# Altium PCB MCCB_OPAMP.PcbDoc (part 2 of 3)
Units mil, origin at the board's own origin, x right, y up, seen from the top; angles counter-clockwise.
Board outline 3937.01 x 3937.01 mil, 2 copper layers (Top Layer, Bottom Layer), stack 62 mil thick; 238 components, 115 nets, 518 pads, 159 vias.
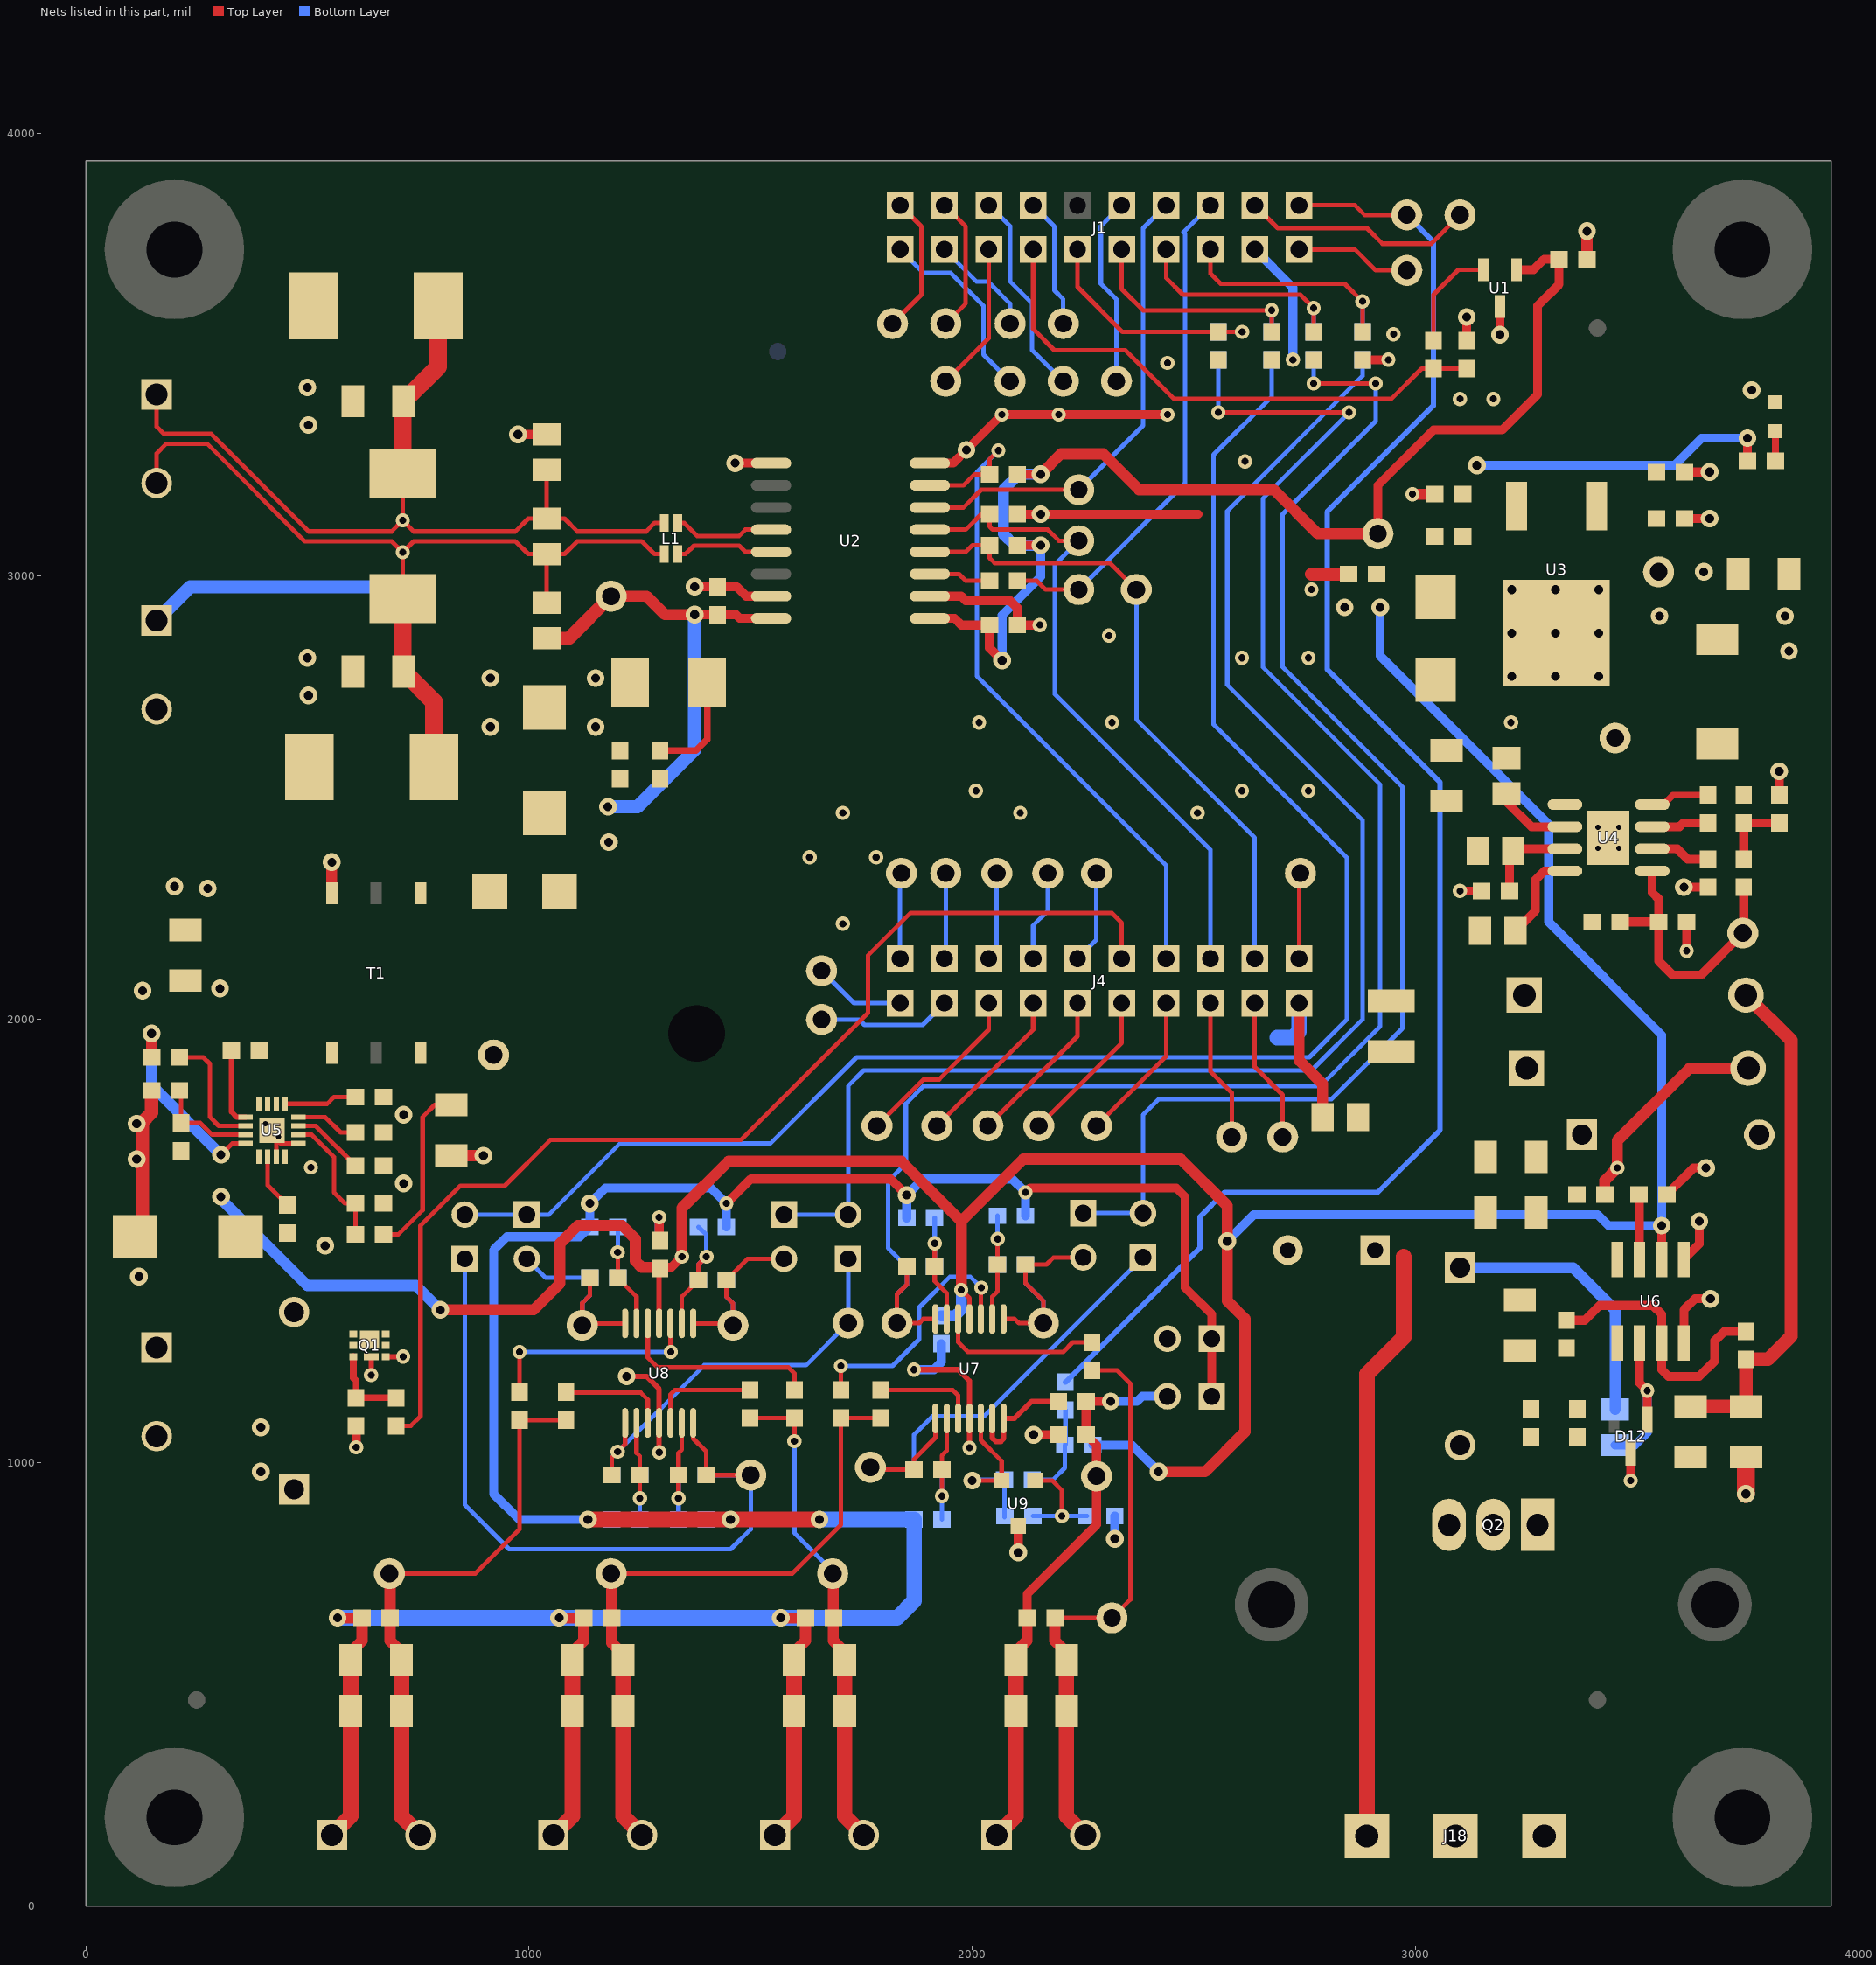
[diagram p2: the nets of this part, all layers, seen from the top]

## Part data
C1 C2 C10 C11 C15 C20 C22 C23 C30 C31 C33 C34 C35 C43: "CAP, CERM, 0.1uF, 25V, +/-5%, X7R, 0603"
C3 C12 C21: "CAP, CERM, 1000pF, 1000V, +/-10%, X7R, 1206"
C4 C7: "CAP, CERM, 1uF, 16V, +/-10%, X7R, 0603"
C5 C8 C29: "CAP, CERM, 0.1uF, 50V, +/-10%, X7R, 0603"
C6: "CAP, TA, 4.7uF, 35V, +/-10%, 1.9 ohm, SMD"
C9: "CAP, CERM, 22uF, 16V, +/-10%, X5R, 1206"
C13 C28: "CAP, TA, 47uF, 35V, +/-10%, 0.3 ohm, SMD"
C14: "CAP, CERM, 1uF, 100V, +/-10%, X7R, 1206"
C16 C25: "CAP, CERM, 0.1uF, 100V, +/-10%, X7R, 0805"
C17 C26 C47 C48 C49 C50: "CAP, CERM, 0.01uF, 25V, +/-5%, C0G/NP0, 0603"
C18: "CAP, CERM, 3300pF, 50V, +/-10%, X7R, 0603"
C19: "CAP, CERM, 1uF, 25V, +/-10%, X5R, 0603"
C24: "CAP, CERM, 22uF, 16V, +/-20%, X5R, 1206"
C27: "CAP, AL, 100uF, 100V, +/-20%, 0.12 ohm, TH"
C32 C36 C37 C38 C39 C40 C41 C42 C44 C45 C46: "CAP, CERM, 100pF, 25V, +/-10%, X7R, 0603"
D1 D3 D5: "Diode, TVS 15V 1500W BIDIR 5% SMC"
D2: "LED SmartLED Green 570NM"
D4: "Diode, Zener, 5.1V, 5W, SMB"
D6: "Diode, Schottky, 20V, 1A, SMA"
D7: "Diode, Zener, 39V, 1W, DO41"
D8: "Diode, Zener, 16V, 1W, DO41"
D9 D11: "Diode, P-N, 1000V, 1A, TH"
D10: library part 1N4007, "Diode, P-N, 1100V, 1A, TH"
D12: "Diode, Switching, 200V, 0.2A, SOT-23"
FB1: library part MMZ1608B102C, "FERRITE CHIP 1000 OHM 300MA 0603"
FID1 FID2 FID3 FID4 FID5 FID6: "Fiducial mark.  There is nothing to buy or mount."
H1 H2 H4 H5: "Machine Screw, Round, #4-40 x 1/4, Nylon, Philips panhead"
H3: library part "MH 3_0.5MM", "Mountin hole, NPTH Drill 3.2mm"
H6 H7 H8 H9: "Standoff, Hex, 0.5\"L #4-40 Nylon"
HS1: library part HEATSINK_513201, "HEATSINK TO-220 W/PINS 1.5\"TALL"
J1 J4: "Header, Male 2x10-pin, 100mil spacing"
J2 J3 J11 J14 J15 J16 J17: "TERMINAL BLOCK 5.08MM VERT 2POS, TH"
J5 J6 J7 J8 J9 J10 J12 J13: "Header, Male 2-pin, 100mil spacing,"
J18: "Terminal Block, 3-pin, 15-A, 5.1mm"
L1: library part IND_ACM2012_SERIES, "Inductor, Common Mode Filter SMD"
L2: library part IND_SRR7032-221M, "Inductor, 220uH .30A SMD"
L3: library part IND_B82422H1332K, "Inductor, Chip, 3.3uH 770MA 1210 10%"
LBL1: library part THT-14-423-10, "Thermal Transfer Printable Labels, 0.650\" W x 0.200\" H - 10,000 per roll"
Logo1: library part TI_Logo, "Texas Instrument Corporate Signature"
Q1: "MOSFET, N-CH, 30V, 22A, SON 2X2 MM"
Q2: "MOSFET, N-CH, 60V, 50A, TO-220AB"
R1 R40 R67 R68 R69 R70 R71: "RES, 100 ohm, 1%, 0.1W, 0603"
R2 R9: "RES, 470 ohm, 1%, 0.125W, 0805"
R3 R39: "RES, 300 ohm, 5%, 0.1W, 0603"
R4 R5 R7: "RES, 10k ohm, 5%, 0.1W, 0603"
R6: "RES, 120 ohm, 5%, 0.125W, 0805"
R8: "RES, 10.0 ohm, 1%, 0.1W, 0603"
R10: "RES, 200 ohm, 1%, 0.1W, 0603"
R11: "RES, 63.4k ohm, 1%, 0.1W, 0603"
R12: "RES, 121k ohm, 0.1%, 0.125W, 0805"
R13 R22: "RES, 10.0k ohm, 1%, 0.1W, 0603"
R14: "RES, 1.00k ohm, 1%, 0.1W, 0603"
R15: "RES, 9.76k ohm, 1%, 0.1W, 0603"
R16: "RES, 53.6k ohm, 0.1%, 0.125W, 0805"
R17 R25: "RES, 100k ohm, 1%, 0.1W, 0603"
R18: "RES, 21.5k ohm, 1%, 0.1W, 0603"
R19 R63: "RES, 30k ohm, 5%, 0.1W, 0603"
R20: "RES, 280k ohm, 1%, 0.1W, 0603"
R21 R23 R29: "RES, 10.0k ohm, 1%, 0.25W, 1206"
R24: "RES, 43.2k ohm, 1%, 0.1W, 0603"
R26 R27 R28 R59: "RES, 68k ohm, 5%, 0.1W, 0603"
R30: "RES, 1.00Meg ohm, 1%, 0.1W, 0603"
R31 R32 R33 R34 R35 R36 R37 R38 R55 R56 R57 R58 R62 R64 R65 R66: "RES, 10k ohm, 0.01%, 0.063W, 0603"
R41 R42: "RES, 1.00k ohm, 1%, 0.25W, 1206"
R43: "RES, 510 ohm, 0.1%, 0.1W, 0603"
R44 R45 R46: "RES, 27k ohm, 5%, 0.1W, 0603"
R47 R48 R49 R50 R51 R52 R53 R54: "RES, 22 ohm, 5%, 0.25W, 1206"
R60: "RES, 47k ohm, 5%, 0.125W, 0805"
R61: "RES, 470 ohm, 5%, 0.1W, 0603"
R72: "RES, 0 ohm, 5%, 0.1W, 0603"
T1: library part "TRNSFMR 760390015", "Transformer 475uH SMD"
TP1 TP2 TP3 TP4 TP5 TP6 TP7 TP8 TP9 TP10 TP11 TP12 TP13 TP14 TP15 TP16 TP17 TP18 TP19 TP20 TP21 TP22 TP23 TP24 TP25 TP26 TP27 TP28 TP29 TP30 TP31 TP32 TP33 TP34 TP35 TP36 TP37 TP38 TP39 TP40 TP41 TP42 TP43 TP44 TP45 TP46 TP47 TP48: "Test Point, O.040 Hole"
U1: "2.7V, 15.6mV/°C, Temperature Sensor, 3-pin SOT-23"
U2: "IC, ISOLATED RS-485 PROFIBUS TRANSCEIVER"
U3: "IC, 300-mA 40-V LOW-DROPOUT REGULATOR WITH 25-uA QUIESCENT CURRENT"
U4: "100V, 600mA Constant On-Time Synchronous Buck Regulator, DDA0008B"
U5: "IC, DC-DC Converter"
U6: "IC, Dual Differential Comparators, 2-36 Vin"
U7 U8: library part LMV324IPW, "LOW-VOLTAGE RAIL-TO-RAIL OUTPUT OPERATIONAL AMPLIFIERS, PW0014A"
U9: "IC, Micropower Shunt Voltage Reference 100 ppm/°C, 45µA-12mA,  Adjustable"
ZZ1: library part AssemblyNoteLabel
ZZ2 ZZ3 ZZ4: library part AssemblyNote

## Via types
v1: diameter 32, hole 16, Top Layer to Bottom Layer, tented both sides, 69 vias
v2: diameter 40, hole 20, Top Layer to Bottom Layer, tented both sides, 68 vias
v3: diameter 40, hole 20, Top Layer to Bottom Layer, 15 vias
v4: diameter 26, hole 12, Top Layer to Bottom Layer, tented both sides, 6 vias
v5: diameter 32, hole 16, Top Layer to Bottom Layer, 1 vias

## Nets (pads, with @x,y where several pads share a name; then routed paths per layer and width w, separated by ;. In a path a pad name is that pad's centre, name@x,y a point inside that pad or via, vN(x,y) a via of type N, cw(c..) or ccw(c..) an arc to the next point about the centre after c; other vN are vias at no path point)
3.3_REF: J1.1 R72.1 TP1.1 | length 3668
  Top Layer w10: J1.1@2737.01,3837.01 2862.99,3837.01 2885,3815 TP1.1@2980,3815
  Bottom Layer w12: R72.1@2210,1181.5 2513,1484.5 2513,1554.64 2568.36,1610 2914,1610 3055,1751 3055,2535 2800,2790 2800,3145 3040,3385 3040,3755 TP1.1@2980,3815
12V: C5.1 C7.1 C9.1 C18.1 D9.2 D11.1 J11.2 L2.2 R15.2 R22.2 TP15.1 U3.1 | length 231.9
  Top Layer w20: R22.2@3566.5,1605 3626.5,1665 v2(3655,1665) ; v1(3611.5,2155) R15.2@3611.5,2220 ; C18.1@3820,2506.5 v2(3820,2560)
  other v2: 395,980 395,1080 3550,2910 3650,3010
16V_C: C29.1 D8.1 D9.1 R21.1 R23.1 R29.1 U6.8
39V: C25.1 C27.1 D7.1 D10.1 J18.1 L3.1 R21.2 R23.2 R60.2 | length 1955.7
  Top Layer w35: J18.1@2890,158 2890,1200 2973,1283 2973,1465
  Bottom Layer w25: D10.1@3100,1440 3354.97,1440 3450,1344.97 R60.2@3450,1120
B: C48.2 J1.10 R68.2 | length 543.9
  Top Layer w10: J1.10@2337.01,3737.01 2337.01,3647.99 2385,3600 v1(2675,3600) C48.2@2675,3551.5
  Bottom Layer w10: R68.2@2675,3551.5 v1(2675,3600)
B_IP: C38.1 J16.2 R35.1 R36.1 R49.2 R53.2 TP47.1 | length 1105.6
  Top Layer w10: R36.1@1498.54,1100.77 R35.1@1598.54,1100.77 v1(1598.54,1048.54)
  Top Layer w25: TP47.1@1685,750 1686.5,748.5 C38.1@1686.5,650 1686.5,598.5 1712.09,572.91 R49.2@1712.09,555
  Top Layer w35: R49.2@1712.09,555 R53.2@1712.09,440 1712.09,202.91 J16.2@1755,160
  Bottom Layer w10: v1(1598.54,1048.54) 1598.54,841.46 1685,755 TP47.1@1685,750
C5V: C10.2 C13.1 C15.1 D6.1 R9.2 R10.2 TP18.1 U2.16 | length 1119.7
  Top Layer w20: v2(1373.5,2913.5) C10.2@1425,2913.5 1466.5,2913.5 1475,2905 U2.16@1545.87,2905
  Top Layer w25: TP18.1@1185,2955 1265,2955 1306.5,2913.5 v2(1373.5,2913.5)
  Top Layer w30: R9.2@1040,2860 1090,2860 TP18.1@1185,2955
  Bottom Layer w30: v2(1178,2480) 1245,2480 1373.5,2608.5 v2(1373.5,2913.5)
  other v2: 1180,2400
EGND: C3.2 C12.1 D1.1 D5.2 J3.2
  other v2: 502.5,2731 500,2816 502.5,3341 500,3426
FSD: J4.9 R39.1 | length 2533.9
  Top Layer w10: R39.1@700,1083.5 733.5,1083.5 755,1105 755,1535 845,1625 945,1625 1048.01,1728.01 1477.57,1728.01 1765,2015.44 1765,2145 1860,2240 2315,2240 2337.01,2217.99 J4.9@2337.01,2137.01
GND: C1.2 C2.1 C4.2 C5.2 C6.2 C7.2 C8.2 C9.2 C11.1 C14.1 C16.1 C19.2 C21.2 C23.1 C24.2 C25.2 C26.2 C27.2 C28.2 C29.2 C30.2 C31.1 C33.2 C35.1 C43.1 C47.1 C48.1 C49.1 C50.1 D2.1 D8.2 D12.3 J1.4 J4.2 J12.2 J18.2 Q1.4 Q1.7 Q2.3 R5.1 R13.1 R14.1 R18.1 R20.1 R24.1 R41.1 R42.1 R62.1 U1.3 U2.2 U2.8 U3.2 U4.1 U4.9 U5.3 U5.4 U5.5 U5.17 U6.4 U6.5 U7.11 U8.11 U9.3 | length 5033
  Top Layer w10: U5.3@429.9,1690.7 U5.17@429.9,1730 ; U5.17@429.9,1735 429.9,1740.5 U5.17@420.1,1750.3 420.1,1739.8 U5.17@429.9,1730 ; U5.5@479.55,1720.65 439.25,1720.65 U5.17@429.9,1730
  Top Layer w12: v1(643.78,1197.79) Q1.7@643.78,1239.41 ; Q1.4@676.32,1239.41 v1(715.98,1239.41) ; v2(1220,1195) 1265,1195 1293.55,1166.45 U8.11@1293.55,1090.06 v1(1293.55,1023.55) ; v1(1868,1210) 1968,1210 1993.54,1184.46 U7.11@1993.54,1100.06 v1(1993.54,1033.55)
  Top Layer w20: v1(610,1035) C33.2@610,1083.5 ; C31.1@1293.54,1503.76 v1(1293.54,1553.54) ; U2.2@1904.13,2955 1975,2955 1985,2945 2085,2945 2101.5,2928.5 C11.1@2101.5,2890 v1(2152,2890) ; U2.8@1904.13,3255 1956.64,3255 v2(1986.64,3285) v1(2066.64,3365) v1(2440,3365) ; R5.1@2101.5,3140 v2(2154,3140) 2509,3140 ; v2(2103.54,797.54) U9.3@2103.54,857.27 ; v2(2138,1063.29) C35.1@2193.5,1063.29 ; C47.1@2880,3488.5 v1(2938.5,3488.5) ; v1(3100,2290) R13.1@3148.5,2290 ; C2.1@3115,3531.5 v2(3115,3585) ; v2(3190,3545) U1.3@3190,3608.66 ; v1(3485,960) D12.3@3485,1022.6 ; U6.4@3605,1270 3605,1345 3630,1370 v2(3665,1370) ; U6.5@3605,1459 3640,1494 v2(3640,1545) ; v2(3605,2298.5) C19.2@3660,2298.5 ; C7.2@3606.5,3130 v3(3663,3130) ; C5.2@3606.5,3235 v3(3663,3235)
  Top Layer w25: C24.2@825,1692.91 v2(897.09,1692.91) ; J4.2@2737.01,2037.01 2737.01,1907.99 2790,1855 C25.2@2790,1780 ; v5@2997.01,3185 C4.2@3043.5,3185 ; C1.2@3386.5,3715 v2(3386.5,3778.5) ; C29.2@3426.5,1605 3426.5,1636.5 v1(3455,1665) 3455,1727 3618,1890 D8.2@3750,1890
  Top Layer w30: C28.2@127.91,1488.09 127.91,1768.91 148.5,1789.5 R18.1@148.5,1840 ; 2765,3005 C8.2@2848.5,3005
  Top Layer w40: v2(3745,930) R42.1@3745,1012.91
  Bottom Layer w20: 1293.54,1503.76 v1(1293.54,1553.54) ; v1(1868,1210) 1913,1210 1930,1227 C43.1@1930,1268.5 ; v2(2321.5,828.5) R62.1@2321.5,880 ; J1.4@2637.01,3737.01 2723,3651.02 v1(2723,3488.5)
  Bottom Layer w35: 2687.39,1959.36 2723.36,1959.36 2737.01,1973.01 J4.2@2737.01,2037.01
  other v1: 508,1666 1708,2216 1633,2366 1783,2366 1708,2466 2108,2466 2508,2466 2008,2516 2608,2516 2758,2516 2015,2670 2315,2670 3215,2670 2608,2816 2758,2816 2308,2866 2765,2970 2615,3259 2195,3365 3100,3400 3175,3400 2440,3481 2950,3546
  other v2: 120,1420 540,1490 717,1630 115,1685 115,1765 717,1785 128,2065 303,2070 3842,2831 3833,2910 3758,3420
  other v3: 3217,2773.89 3315,2773.89 3413,2773.89 3217,2871.89 3315,2871.89 3413,2871.89 3217,2969.89 3315,2969.89 3413,2969.89
  other v4: 435,1735 405,1765 3411.38,2386.38 3458.62,2386.38 3411.38,2433.62 3458.62,2433.62
  other v5: 2993,3185
N: C50.2 J1.12 R70.2 | length 551.1
  Top Layer w10: J1.12@2237.01,3737.01 2237.01,3652.99 2338.5,3551.5 C50.2@2555,3551.5 v1(2608.5,3551.5)
  Bottom Layer w10: R70.2@2555,3551.5 v1(2608.5,3551.5)
N_IP: C39.1 J17.2 R32.1 R50.2 R54.2 TP48.1 | length 1299.8
  Top Layer w10: C39.1@2186.5,650 TP48.1@2315,650 2357,692 2357,1178 2326.5,1208.5 R32.1@2270,1208.5
  Top Layer w25: C39.1@2185.99,650 2185.99,598.5 2211.58,572.91 R50.2@2211.58,555
  Top Layer w35: R50.2@2212.09,562.91 R50.2@2212.09,555 R54.2@2212.09,440 2212.09,202.91 J17.2@2255,160
NetC4_1: C4.1 FB1.1 R3.2 U3.3 | length 687.5
  Top Layer w20: R3.2@3748.5,3260 v3(3748.5,3311.5)
  Bottom Layer w20: v3(3138,3250) 3583.5,3250 3645,3311.5 v3(3748.5,3311.5)
NetC14_2: C14.2 C16.2 L3.2 R12.2 R16.2 U4.2 | length 177.3
  Top Layer w20: C16.2@3205,2513.5 C16.2@3205,2510 3205,2491 3261,2435 U4.2@3336.57,2435
NetC17_1: C17.1 U4.7 | length 130.1
  Top Layer w20: U4.7@3533.43,2435 3595,2435 3603.5,2443.5 C17.1@3660,2443.5
NetC17_2: C17.2 L2.1 R11.1 TP19.1 U4.8 | length 135.5
  Top Layer w15: U4.8@3533.43,2485 3559,2485 3580.5,2506.5 C17.2@3660,2506.5
NetC18_2: C18.2 C20.2 R11.2 | length 162
  Top Layer w20: C20.2@3740,2361.5 R11.2@3740,2443.5 C18.2@3820,2443.5
NetC19_1: C19.1 U4.6 | length 136.3
  Top Layer w20: U4.6@3533.43,2385 3590,2385 3613.5,2361.5 C19.1@3660,2361.5
NetC20_1: C20.1 R14.2 R15.1 TP26.1 U4.5 | length 643
  Top Layer w20: R14.2@3461.5,2220 R15.1@3548.5,2220 ; U4.5@3533.43,2335 3533.43,2286.57 3548.5,2271.5 R15.1@3548.5,2220 ; C20.1@3740,2298.5 3740,2197 TP26.1@3738,2195 3643,2100 3580,2100 3548.5,2131.5 R15.1@3548.5,2220
NetC22_1: C22.1 T1.1 U5.10 U5.11 U5.12
NetC22_2: C22.2 U5.13 | length 175.3
  Top Layer w12: C22.2@328.5,1930 328.5,1791.5 340.05,1779.95 U5.13@360.55,1779.95
NetC23_2: C23.2 U5.9 | length 165.2
  Top Layer w10: U5.9@449.6,1809.7 544.7,1809.7 560,1825 C23.2@608.5,1825
NetC24_1: C24.1 R25.1 T1.3 TP29.1 | length 397.5
  Top Layer w10: R25.1@671.5,1515 705,1515 760,1570 760,1780 787.09,1807.09 C24.1@825,1807.09
NetC26_1: C26.1 U5.7 | length 166.3
  Top Layer w10: U5.7@479.55,1760.05 518.45,1760.05 C26.1@608.5,1670
NetC32_1: C32.1 R57.2 R59.1 U8.2 | length 308.3
  Top Layer w10: U8.2@1344.73,1314.47 1344.73,1374.95 C32.1@1382.05,1412.27 1382.05,1447.05 v1(1400,1465)
  Bottom Layer w10: R59.1@1382.05,1412.27 1382.05,1447.05 v1(1400,1465) 1400,1514.31 R57.2@1382.05,1532.27
NetC32_2: C32.2 J9.2 R59.2 TP41.1 U8.1 | length 451.9
  Top Layer w10: U8.1@1370.32,1314.47 TP41.1@1455.53,1314.47 ; TP41.1@1460,1310 1460,1360 1445.04,1374.96 C32.2@1445.04,1412.27 1492.77,1460 J9.2@1575,1460
  Bottom Layer w10: R59.2@1445.04,1412.27 1445.04,1374.96 1460,1360 TP41.1@1460,1310
NetC33_1: C33.1 Q1.3 R39.2 | length 175.5
  Top Layer w15: Q1.3@603.68,1239.41 603.68,1191.32 610,1185 C33.1@610,1146.5 ; C33.1@620,1146.5 R39.2@700,1146.5
NetC34_1: C34.1 R29.2 R30.2 R43.1 U6.1
NetC34_2: C34.2 Q2.1 R43.2
NetC40_1: C40.1 R26.1 R55.2 U7.2 | length 295.6
  Top Layer w10: U7.2@2044.72,1324.47 2044.72,1374.72 2057.05,1387.05 R26.1@2057.05,1447.27 v1(2057.05,1505)
  Bottom Layer w10: C40.1@2057.05,1447.27 v1(2057.05,1505) R55.2@2057.05,1557.27
NetC40_2: C40.2 J5.2 R26.2 TP39.1 U7.1 | length 527.8
  Top Layer w10: U7.1@2070.32,1324.47 2095.53,1324.47 2105,1315 TP39.1@2160,1315 2160,1365 2120.04,1404.96 R26.2@2120.04,1447.27 2167.27,1447.27 2183.29,1463.29 J5.2@2250,1463.29
  Bottom Layer w10: C40.2@2120.04,1447.27 2120.04,1404.96 2160,1365 TP39.1@2160,1315
NetC41_1: C41.1 R27.1 R56.2 U7.6 | length 291.8
  Top Layer w10: v1(1915,1495) R27.1@1915.04,1442.27 1915.04,1409.96 1942.36,1382.64 U7.6@1942.36,1324.47
  Bottom Layer w10: v1(1915,1495) v1(1915,1495) C41.1@1915.04,1442.27 ; v1(1915,1495) R56.2@1915.04,1552.27
NetC41_2: C41.2 R27.2 R70.1 TP38.1 U7.7 | length 3896.7
  Top Layer w10: R27.2@1852.05,1442.27 1852.05,1402.05 1830,1380 TP38.1@1830,1315 1880,1315 1889.47,1324.47 U7.7@1916.77,1324.47 ; v1(2555,3370) v1(2850,3370)
  Bottom Layer w10: TP38.1@1830,1315 1830,1380 1852.05,1402.05 C41.2@1852.05,1442.27 1810,1484.31 1810,1635 1850,1675 1850,1810 1890,1850 2785,1850 2920,1985 2920,2530 2655,2795 2655,3175 v1(2850,3370) ; v1(2555,3370) R70.1@2555,3488.5
NetC42_1: C42.1 R28.1 R58.2 U8.6 | length 293
  Top Layer w10: v1(1200.04,1474.96) R28.1@1200.04,1417.27 1242.37,1374.94 U8.6@1242.37,1314.47
  Bottom Layer w10: C42.1@1200.04,1417.27 v1(1200.04,1474.96) R58.2@1200.04,1532.27
NetC42_2: C42.2 J8.2 R28.2 TP40.1 U8.7 | length 487
  Top Layer w10: R28.2@1137.05,1417.27 1137.05,1377.05 1120,1360 TP40.1@1120,1310 1124.47,1314.47 U8.7@1216.78,1314.47
  Bottom Layer w10: J8.2@995,1460 1037.73,1417.27 C42.2@1137.05,1417.27 1137.05,1377.05 1120,1360 TP40.1@1120,1310
NetC44_1: C44.1 R44.1 R65.2 U7.9 | length 292.3
  Top Layer w10: v1(1931.5,925) R44.1@1931.5,985 1931.5,1016.5 1942.36,1027.36 U7.9@1942.36,1100.06
  Bottom Layer w10: R65.2@1931.5,872.27 v1(1931.5,925) 1931.5,935 C44.1@1931.5,985
NetC44_2: C44.2 J6.1 R44.2 TP42.1 U7.8 | length 1096.8
  Top Layer w10: TP42.1@1770,990 1775,985 R44.2@1868.5,985 1868.5,1008.5 1916.77,1056.77 U7.8@1916.77,1100.06
  Bottom Layer w10: TP42.1@1770,990 1775,985 C44.2@1868.5,985 1868.5,1063.5 1910,1105 2026.71,1105 J6.1@2385,1463.29
NetC45_1: C45.1 R46.1 R66.2 U8.9 | length 273.2
  Top Layer w10: U8.9@1242.37,1090.06 1242.37,1022.63 1250.04,1014.96 R46.1@1250.04,972.27 v1(1250.04,920)
  Bottom Layer w10: R66.2@1250.04,872.27 v1(1250.04,920) C45.1@1250.04,972.27
NetC45_2: C45.2 J10.1 R46.2 TP37.1 U8.8 | length 973.3
  Top Layer w10: R46.2@1187.05,972.27 1187.05,1012.05 v1(1200,1025) 1216.78,1041.78 U8.8@1216.78,1090.06
  Bottom Layer w10: C45.2@1187.05,972.27 1187.05,1012.05 v1(1200,1025) 1395,1220 1625,1220 TP37.1@1720,1315 J10.1@1720,1460
NetC46_1: C46.1 R45.1 R64.2 U8.13 | length 273.2
  Top Layer w10: v1(1337.05,920) R45.1@1337.05,972.27 1337.05,1022.05 1344.73,1029.73 U8.13@1344.73,1090.06
  Bottom Layer w10: R64.2@1337.05,872.27 v1(1337.05,920) C46.1@1337.05,972.27
NetC46_2: C46.2 J7.1 R45.2 TP43.1 U8.14 | length 1712.3
  Top Layer w10: U8.14@1370.32,1090.06 1370.32,1054.68 1400.04,1024.96 R45.2@1400.04,972.27 TP43.1@1500,972.27
  Bottom Layer w10: J7.1@855,1460 855,905 955,805 1455,805 1500,850 TP43.1@1500,972.27 C46.2@1400.04,972.27
NetD2_2: D2.2 R3.1 | length 68.1
  Top Layer w15: D2.2@3810,3327.52 3811.5,3326.02 R3.1@3811.5,3260
NetD4_1: D4.1 R10.1 | length 245.6
  Top Layer w15: R10.1@1295,2606.5 1376.5,2606.5 1402,2632 D4.1@1402,2760
NetD6_2: D6.2 T1.4
NetD7_2: D7.2 R31.2 R41.2 R42.2 | length 1166.7
  Top Layer w30: R41.2@3620,1127.09 R42.2@3745,1127.09 R31.2@3745,1233.5 3795,1233.5 3847.01,1285.51 3847.01,1952.99 D7.2@3745,2055
NetD10_2: D10.2 J18.3 Q2.2
NetD11_2: D11.2 J11.1 Q1.1 Q1.2 Q1.5 Q1.6 Q1.8
NetD12_1: D12.1 R60.1 U6.2 | length 358.8
  Top Layer w20: U6.2@3505,1270 3505,1180 v1(3522.4,1162.6) D12.1@3522.4,1097.4
  Bottom Layer w20: R60.1@3450,1040 3495,1040 3522.4,1067.4 v1(3522.4,1162.6)
NetJ1_2: J1.2 TP3.1 | length 262.5
  Top Layer w10: J1.2@2737.01,3737.01 2862.99,3737.01 2910,3690 TP3.1@2980,3690
NetJ1_3: J1.3 TP2.1 | length 526
  Top Layer w10: J1.3@2637.01,3837.01 2689.02,3785 2890,3785 2925,3750 3035,3750 TP2.1@3100,3815
NetJ1_9: J1.9 TP11.1 | length 431
  Bottom Layer w10: TP11.1@2325,3440 2325,3625 2290,3660 2290,3790 J1.9@2337.01,3837.01
NetJ1_13: J1.13 TP7.1 | length 295.2
  Bottom Layer w10: J1.13@2137.01,3837.01 2185,3789.02 2185,3645 2205,3625 TP7.1@2205,3570
NetJ1_15: J1.15 TP10.1 | length 467.2
  Bottom Layer w10: J1.15@2037.01,3837.01 2037.99,3837.01 2085,3790 2085,3665 2135,3615 2135,3510 TP10.1@2205,3440
NetJ1_16: J1.16 TP8.1 | length 337.2
  Top Layer w10: TP8.1@1940,3440 2037,3537 J1.16@2037.01,3737.01
NetJ1_17: J1.17 TP5.1 | length 305.5
  Top Layer w10: J1.17@1937.01,3837.01 1985,3789.02 1985,3615 TP5.1@1940,3570
NetJ1_18: J1.18 TP6.1 | length 243.5
  Bottom Layer w10: J1.18@1937.01,3737.01 2009.02,3665 2035,3665 2085,3615 TP6.1@2085,3570
NetJ1_19: J1.19 TP4.1 | length 313.8
  Top Layer w10: TP4.1@1820,3570 1885,3635 1885,3789.02 J1.19@1837.01,3837.01
NetJ1_20: J1.20 TP9.1 | length 435.5
  Bottom Layer w10: J1.20@1837.01,3737.01 1890,3684.02 1950.98,3684.02 2025,3610 2025,3500 TP9.1@2085,3440
NetJ4_1: J4.1 TP25.1 | length 190
  Top Layer w10: J4.1@2737.01,2137.01 TP25.1@2737.01,2327.01
NetJ4_4: J4.4 TP36.1 | length 328.1
  Top Layer w10: J4.4@2637.01,2037.01 2637.01,1892.99 2700,1830 TP36.1@2700,1735
NetJ4_6: J4.6 TP35.1 | length 321.9
  Top Layer w10: J4.6@2537.01,2037.01 2537.01,1882.99 2585,1835 TP35.1@2585,1735
NetJ4_8: J4.8 TP34.1 | length 342
  Top Layer w10: TP34.1@2280,1760 2437.01,1917.01 J4.8@2437.01,2037.01
NetJ4_10: J4.10 TP33.1 | length 354.5
  Top Layer w10: TP33.1@2150,1760 2337.01,1947.01 J4.10@2337.01,2037.01
NetJ4_11: J4.11 TP24.1 | length 210.8
  Bottom Layer w10: J4.11@2237.01,2137.01 2280,2180 TP24.1@2280,2330
NetJ4_12: J4.12 TP32.1 | length 360.7
  Top Layer w10: TP32.1@2035,1760 2237.01,1962.01 J4.12@2237.01,2037.01
NetJ4_13: J4.13 TP23.1 | length 206.7
  Bottom Layer w10: J4.13@2137.01,2137.01 2137.01,2212.01 2170,2245 TP23.1@2170,2330
NetJ4_14: J4.14 TP31.1 | length 366.9
  Top Layer w10: TP31.1@1920,1760 2137.01,1977.01 J4.14@2137.01,2037.01
NetJ4_15: J4.15 TP22.1 | length 200.4
  Bottom Layer w10: J4.15@2037.01,2137.01 2055,2155 TP22.1@2055,2330
NetJ4_16: J4.16 TP30.1 | length 401.9
  Top Layer w10: TP30.1@1785,1760 1890,1865 1925,1865 2037.01,1977.01 J4.16@2037.01,2037.01
NetJ4_17: J4.17 TP21.1 | length 190
  Bottom Layer w10: J4.17@1940,2140 TP21.1@1940,2330
NetJ4_18: J4.18 TP28.1 | length 302.3
  Bottom Layer w10: TP28.1@1660,2000 1745,2000 1757,1988 1888,1988 J4.18@1937.01,2037.01
NetJ4_19: J4.19 TP20.1 | length 194.2
  Bottom Layer w10: J4.19@1837.01,2137.01 1837.01,2327.01 TP20.1@1840,2330
NetJ4_20: J4.20 TP27.1 | length 207.2
  Bottom Layer w10: TP27.1@1660,2110 1732.99,2037.01 J4.20@1837.01,2037.01
NetJ5_1: J5.1 J6.2 R69.1 | length 2869.8
  Top Layer w10: v1(2770,3435) v1(2910,3435)
  Bottom Layer w10: J5.1@2250,1563.29 J6.2@2385,1563.29 2385,1785 2420,1820 2810,1820 2970,1980 2970,2525 2700,2795 2700,3140 2910,3350 v1(2910,3435) ; v1(2770,3435) R69.1@2770,3488.5
NetJ7_2: J7.2 J8.1 R68.1 | length 3839.7
  Bottom Layer w10: J7.2@855,1560 1045,1560 1205,1720 1544,1720 1739,1915 2760,1915 2845,2000 2845,2365 2544,2666 2544,3274 2675,3405 R68.1@2675,3488.5
NetJ9_1: J9.1 J10.2 R67.1 | length 3398.3
  Bottom Layer w10: J9.1@1575,1560 J10.2@1720,1560 1720,1850 1755,1885 2765,1885 2880,2000 2880,2450 2575,2755 2575,3147 2880,3452 R67.1@2880,3488.5
NetL1_1: L1.1 U2.13 | length 224.5
  Top Layer w10: L1.1@1335,3050 1353,3050 1372,3069 1474,3069 1488,3055 U2.13@1545.87,3055
NetL1_2: L1.2 U2.12 | length 228.7
  Top Layer w10: L1.2@1335,3120 1350,3120 1379,3091 1474,3091 1488,3105 U2.12@1545.87,3105
NetR1_1: R1.1 U1.2 | length 239.4
  Top Layer w10: R1.1@3040,3531.5 3040,3635 3096.34,3691.34 U1.2@3152.6,3691.34
NetR8_2: R8.2 U2.3 | length 140.6
  Top Layer w10: U2.3@1904.13,3005 1970,3005 1985,2990 R8.2@2038.5,2990
NetR12_1: R12.1 R13.2 U4.3 | length 217.1
  Top Layer w20: R13.2@3211.5,2290 3211.5,2380 R12.1@3220,2380 3225,2385 U4.3@3336.57,2385
NetR16_1: R16.1 U4.4 | length 208.5
  Top Layer w20: R16.1@3225,2200 3270,2245 3270,2315 3290,2335 U4.4@3336.57,2335
NetR17_1: R17.1 U5.14 | length 283.5
  Top Layer w10: R17.1@211.5,1915 265,1915 280,1900 280,1780 299.95,1760.05 U5.14@360.55,1760.05
NetR18_2: R18.2 R19.1 U5.15 | length 226.4
  Top Layer w10: R18.2@215,1836.5 R19.1@215,1766.5 258.5,1766.5 284.65,1740.35 U5.15@360.55,1740.35
NetR20_2: R20.2 U5.8 | length 143.3
  Top Layer w10: U5.8@479.55,1779.75 540.25,1779.75 575,1745 R20.2@608.5,1745
NetR22_1: R22.1 U6.7 | length 146.6
  Top Layer w20: R22.1@3503.5,1605 3505,1603.5 U6.7@3505,1459
NetR24_2: R24.2 R25.2 U5.6 | length 310.2
  Top Layer w10: U5.6@479.55,1740.35 509.65,1740.35 560,1690 560,1610 585,1585 R24.2@608.5,1585 R25.2@608.5,1515
NetR30_1: R30.1 R31.1 U6.3 | length 626.8
  Top Layer w20: R30.1@3340,1321.5 3381.5,1321.5 3415,1355 3535,1355 3555,1335 U6.3@3555,1270 3555,1210 3570,1195 3640,1195 3675,1230 3675,1275 3696.5,1296.5 R31.1@3745,1296.5
NetR32_2: R32.2 U7.5 | length 372.5
  Top Layer w10: U7.5@1967.95,1324.47 1967.95,1272.05 1990,1250 2205,1250 2226.5,1271.5 R32.2@2270,1271.5
NetR33_2: R33.2 U7.3 | length 578.6
  Top Layer w10: R33.2@1703.54,1163.76 v1(1703.54,1218.54) ; U7.3@2019.13,1324.47 v1@2019.13,1395.87
  Bottom Layer w10: v1(1703.54,1218.54) 1820,1218.54 1880,1278.54 1880,1350.46 1949.54,1420 1995,1420 v1(2020,1395)
NetR34_2: R34.2 U7.10 | length 231.2
  Top Layer w10: R34.2@1793.54,1163.76 1956.24,1163.76 1967.95,1152.05 U7.10@1967.95,1100.06
NetR35_2: R35.2 U8.5 | length 460.4
  Top Layer w10: U8.5@1267.96,1314.47 1267.96,1237.04 1290,1215 1585,1215 1598.54,1201.46 R35.2@1598.54,1163.76
NetR36_2: R36.2 U8.12 | length 247.5
  Top Layer w10: U8.12@1319.14,1090.06 1319.14,1154.14 1328.76,1163.76 R36.2@1498.54,1163.76
NetR37_2: R37.2 U8.3 | length 496.3
  Top Layer w10: R37.2@978.54,1158.76 v1(978.54,1250) ; v1@1319.14,1250.86 U8.3@1319.14,1314.47
  Bottom Layer w10: v1(978.54,1250) v1(1320,1250)
NetR38_2: R38.2 U8.10 | length 243.3
  Top Layer w10: R38.2@1083.54,1158.76 1251.24,1158.76 1267.96,1142.04 U8.10@1267.96,1090.06
NetR40_1: R40.1 U7.13 U7.14 | length 260.2
  Top Layer w12: U7.13@2044.72,1100.06 2044.72,1056.28 2053,1048 2064,1048 2070.32,1054.32 U7.14@2070.32,1100.06 2095.06,1100.06 2133.29,1138.29 R40.1@2193.5,1138.29
NetR61_1: R61.1 R63.2 U7.12 U9.2 | length 384.3
  Top Layer w10: v2(1999.77,959.77) U9.2@2066.04,959.77 2066.04,1003.96 2019.13,1050.87 U7.12@2019.13,1100.06
  Bottom Layer w10: v2(1999.77,959.77) 2002.27,962.27 R61.1@2072.05,962.27 R63.2@2072.05,877.27
NetR61_2: R61.2 R71.2 R72.2 | length 215
  Bottom Layer w10: R61.2@2135.04,962.27 2182.27,962.27 2208.5,988.5 R71.2@2208.5,1040 2210,1041.5 R72.2@2210,1118.5
NetR62_2: R62.2 R63.1 U9.1 | length 250
  Top Layer w10: U9.1@2141.04,959.77 2180.23,959.77 2202,938 v1(2202,880)
  Bottom Layer w10: R63.1@2136.5,880 v1(2202,880) R62.2@2258.5,880
PGND: C10.1 C13.2 C15.2 C21.1 D4.2 J3.1 R2.1 T1.6 U2.9 U2.15 | length 1018.8
  Top Layer w20: v2(975,3320) R2.1@1040,3320 ; v2(1373.5,2976.5) C10.1@1425,2976.5 1468.5,2976.5 1490,2955 U2.15@1545.87,2955 ; v2(1465,3255) U2.9@1545.87,3255
  Top Layer w25: T1.6@555,2284.84 v2(555,2355)
  Bottom Layer w30: J3.1@160,2900 236,2976 750,2976
  other v2: 275,2295.5 200,2300 913,2660 1150,2660 913,2770 1150,2770
R: C47.2 J1.6 R67.2 | length 560.1
  Top Layer w10: J1.6@2537.01,3737.01 2537.01,3682.99 2560,3660 2840,3660 v1(2880,3620) C47.2@2880,3551.5
  Bottom Layer w10: R67.2@2880,3551.5 v1(2880,3620)
R_IP: C36.1 J14.2 R37.1 R38.1 R47.2 R51.2 TP45.1 | length 1301.7
  Top Layer w10: TP45.1@686.5,748.5 687.99,750 878.54,750 978.54,850 R37.1@978.54,1095.77 R38.1@1083.54,1095.77
  Top Layer w25: TP45.1@686.5,748.5 C36.1@686.5,650 686.5,598.5 712.09,572.91 R47.2@712.09,555
  Top Layer w35: R47.2@712.09,555 R51.2@712.09,440 712.09,202.91 J14.2@755,160
RS485_CHIP_EN: J4.7 R4.1 U2.7 | length 1550
  Top Layer w10: U2.7@1904.13,3205 1980,3205 2005,3230 R4.1@2038.5,3230 2038.5,3263.5 v1(2058.5,3283.5)
  Bottom Layer w10: v1(2058.5,3283.5) 2010,3235 2010,2775 2437.01,2347.99 J4.7@2437.01,2137.01
RS485_ISO_A: C3.1 D1.2 D3.1 J2.1 L1.3 R2.2 R6.1 | length 1995.4
  Top Layer w10: J2.1@160,3410 160,3337.58 176.58,3321 282.95,3321 ; 282.82,3321.12 282.95,3321 ; D3.1@715,3230.49 v1(715,3126) ; R2.2@1040,3240 R6.1@1040,3130 ; L1.3@1305,3120 1283,3120 1264,3101 1109,3101 1080,3130 R6.1@1040,3130 ; 282.95,3321 502.95,3101 690,3101 v1(715,3126) ; v1(715,3126) 740,3101 969,3101 998,3130 R6.1@1040,3130
  Top Layer w40: D3.1@715,3230.49 715,3392.91 C3.1@717.09,3395 795.15,3473.06 D1.2@795.15,3610
RS485_ISO_B: C12.2 D3.2 D5.1 J2.2 L1.4 R6.2 R9.1 | length 1992.3
  Top Layer w10: J2.2@160,3210 160,3277.26 181.74,3299 273.83,3299 493.83,3079 500.89,3079 690,3079 v1(715,3054) ; D3.2@715,2949.51 v1(715,3054) ; R9.1@1040,2940 R6.2@1040,3050 ; L1.4@1305,3050 1283,3050 1254,3079 1109,3079 1080,3050 R6.2@1040,3050 ; v1(715,3054) 740,3079 969,3079 998,3050 R6.2@1040,3050
  Top Layer w40: D3.2@715,2949.51 715,2787.09 C12.2@717.09,2785 785.49,2716.59 D5.1@785.49,2570
RS485_RX_EN: J4.3 R7.1 TP17.1 U2.4 | length 1473.8
  Top Layer w10: U2.4@1904.13,3055 1985,3055 2000,3070 R7.1@2038.5,3070 2038.5,3041.5 2050,3030 2310,3030 TP17.1@2370,2970
  Bottom Layer w10: TP17.1@2370,2970 2370,2677.01 2637.01,2410 J4.3@2637.01,2137.01
RS485_TX_EN: J4.5 R5.2 TP14.1 U2.5 | length 1483.8
  Top Layer w10: U2.5@1904.13,3105 1985,3105 R5.2@2020,3140 ; R5.2@2038.5,3140 2038.5,3112.2 2045.7,3105 2170,3105 2195,3080 TP14.1@2240,3080
  Bottom Layer w10: TP14.1@2240,3080 2186,3026 2186,2734 2537.01,2382.99 J4.5@2537.01,2137.01
TEMP: C2.2 J1.14 R1.2 | length 1250.8
  Top Layer w10: J1.14@2137.01,3737.01 2137.01,3557.99 2185,3510 2345,3510 2455,3400 2945,3400 3013.5,3468.5 R1.2@3040,3468.5 C2.2@3115,3468.5
UC3.3V: C1.1 C6.1 C8.1 C11.2 C28.1 C30.1 C31.2 C43.2 FB1.2 R4.2 R7.2 R17.2 R19.2 R71.1 TP13.1 U1.1 U2.1 U5.1 U5.2 U5.16 U6.6 U7.4 U8.4 | length 10377.3
  Top Layer w10: v2(305,1695) 330.65,1720.65 U5.16@360.55,1720.65 ; U5.2@410.2,1690.7 410.2,1626.3 C30.1@455,1581.5 ; v1(1975,1390) 1993.54,1371.46 U7.4@1993.54,1324.47
  Top Layer w12: U8.4@1293.55,1314.47 C31.2@1293.55,1440.77
  Top Layer w20: C31.2@1293.54,1440.77 1320.77,1440.77 v1(1345,1465) ; U2.1@1904.13,2905 1960,2905 1975,2890 C11.2@2038.5,2890 2038.5,2838.5 v2(2067.01,2810) ; R7.2@2101.5,3070 v2(2154,3070) ; R4.2@2101.5,3230 v2(2154,3230) ; TP13.1@2915,3096 2915,3205 3040,3330 3195,3330 3275,3410 3275,3610 3323.5,3658.5 C1.1@3323.5,3715 3289.45,3715 3265.79,3691.34 U1.1@3227.4,3691.34 ; U6.6@3555,1459 v2(3555,1535)
  Top Layer w25: R17.2@148.5,1915 v2(148.5,1968.5) ; v2(800,1345) 1010,1345 1070,1405 1070,1495 1110,1535 1210,1535 1240,1505 1240,1455 1254.23,1440.77 C31.2@1293.55,1440.77 ; v1(1345,1465) 1345,1575 1450,1680 1840,1680 1975,1545 ; v1(1975,1390) 1975,1545 ; v2(2154,3230) 2200,3276 2295,3276 2376,3195 2680,3195 2779,3096 TP13.1@2915,3096 ; v2(2420,980) 2525,980 2615,1070 2615,1325 2575,1365 v2(2575,1500) 2575,1580 2470,1685 2115,1685 1975,1545
  Bottom Layer w20: v2(2067.01,2810) 2067.01,2912.01 2154,2999 v2(2154,3070) ; R71.1@2271.5,1040 2360,1040 v2(2420,980) ; v2(2575,1500) 2635,1560 3410,1560 3435,1535 v2(3555,1535) 3555,1965 3300,2220 3300,2440 2920,2820 v3(2920,2930)
  Bottom Layer w25: v2(148.5,1968.5) 148.5,1851.5 v2(305,1695) ; v2@305,1595 500,1400 745,1400 v2(800,1345) ; C43.2@1930,1331.5 1961.5,1331.5 1975,1345 v1(1975,1390) ; v2(2154,3070) 2095,3070 2070,3095 2070,3195 2105,3230 v2(2154,3230)
  other v2: 305,1600
  other v3: 2840,2930
UCA1RXD: J1.5 R8.1 TP16.1 | length 1140
  Top Layer w10: R8.1@2101.5,2990 2145,2990 2165,2970 TP16.1@2240,2970
  Bottom Layer w10: TP16.1@2240,2970 2480.01,3210.01 2480.01,3772.39 2476.2,3776.2 J1.5@2537.01,3837.01
UCA1TXD: J1.7 TP12.1 U2.6 | length 1076
  Top Layer w10: U2.6@1904.13,3155 1980,3155 2020,3195 TP12.1@2240,3195
  Bottom Layer w10: TP12.1@2240,3195 2385,3340 2385,3785 J1.7@2437.01,3837.01
VCC/2: C35.2 C39.2 J13.2 J17.1 R40.2 R50.1 R54.1 TP44.1 | length 1269.6
  Top Layer w20: C39.2@2123.5,650 2123.5,703.5 2280,860 TP44.1@2280,970 2280,1039.79 C35.2@2256.5,1063.29 R40.2@2256.5,1138.29 v2(2312,1138.29)
  Top Layer w25: R50.1@2097.41,555 2097.41,572.91 2123,598.5 C39.2@2123,650
  Top Layer w35: J17.1@2055,160 2097.91,202.91 R54.1@2097.91,440 R50.1@2097.91,555
  Bottom Layer w20: v2(2312,1138.29) 2371.29,1138.29 2383,1150 J13.2@2440,1150
VREF_PH: C36.2 C37.2 C38.2 J12.1 J13.1 J14.1 J15.1 J16.1 R47.1 R48.1 R49.1 R51.1 R52.1 R53.1 R55.1 R56.1 R57.1 R58.1 R64.1 R65.1 R66.1 | length 7245.1
  Top Layer w20: v1(1445,1585) 1500,1640 1815.82,1640 v2(1852.05,1603.77) ; v1(2120,1610) 2130,1620 2460,1620 2480,1600 2480,1395 2540,1335 J12.1@2540,1280 J13.1@2540,1150
  Top Layer w25: v2(568,650) C36.2@623.5,650 623.5,598.5 597.91,572.91 R47.1@597.91,555 ; v2(1068,650) C37.2@1120,650 ; R48.1@1094.41,556.5 1094.41,569.41 R48.1@1097.91,572.91 ; R48.1@1097.91,555 R48.1@1097.91,572.91 ; C37.2@1120,651.5 C37.2@1120,650 ; v2(1568,650) C38.2@1623.5,650 1623.5,598.5 1597.91,572.91 R49.1@1597.91,555 ; R48.1@1097.91,572.91 1123.5,598.5 C37.2@1123.5,650 C37.2@1120,650
  Top Layer w35: J14.1@555,160 597.91,202.91 R51.1@597.91,440 R47.1@597.91,555 ; J15.1@1055,160 1097.91,202.91 R52.1@1097.91,440 R48.1@1097.91,555 ; v2(1132.78,872.27) v2(1454.31,872.27) v2(1655,872.27) ; J16.1@1555,160 1597.91,202.91 R53.1@1597.91,440 R49.1@1597.91,555
  Bottom Layer w20: R66.1@1187.05,872.27 v2(1132.78,872.27) 977.73,872.27 920,930 920,1480 950,1510 1114.78,1510 R58.1@1137.05,1532.27 v2(1137.05,1585) 1172.05,1620 1410,1620 v1(1445,1585) v1(1445,1585) R57.1@1445.04,1532.27 ; R64.1@1400.04,872.27 v2(1454.31,872.27) ; R56.1@1852.05,1552.27 v2(1852.05,1603.77) 1888.28,1640 2090,1640 v1(2120,1610) v1(2120,1610) R55.1@2120.04,1557.27
  Bottom Layer w35: v2(568,650) v2(1068,650) v2(1568,650) 1830,650 1868.5,688.5 R65.1@1868.5,872.27 v2(1655,872.27)
Y: C49.2 J1.8 R69.2 | length 532.2
  Top Layer w10: J1.8@2437.01,3737.01 2437.01,3672.99 2475,3635 2740,3635 v1(2770,3605) C49.2@2770,3551.5
  Bottom Layer w10: R69.2@2770,3551.5 v1(2770,3605)
Y_IP: C37.1 J15.2 R33.1 R34.1 R48.2 R52.2 TP46.1 | length 1513.9
  Top Layer w10: TP46.1@1185,750 1593.54,750 1703.54,860 R33.1@1703.54,1100.77 R34.1@1793.54,1100.77
  Top Layer w25: TP46.1@1185,750 1186.5,748.5 C37.1@1186.5,650 1186.5,593.5 R48.2@1212.09,567.91
  Top Layer w35: R48.2@1212.09,567.91 R48.2@1212.09,555 R52.2@1212.09,440 1212.09,202.91 J15.2@1255,160
pads on no net: D12.2 FID1.1 FID2.1 FID3.1 FID4.1 FID5.1 FID6.1 H1.1 H2.1 H3.1 H4.1 H5.1 HS1.1 HS1.2 J1.11 Logo1.0 T1.2 T1.5 U2.10 U2.11 U2.14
